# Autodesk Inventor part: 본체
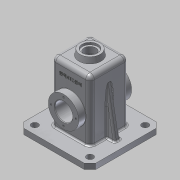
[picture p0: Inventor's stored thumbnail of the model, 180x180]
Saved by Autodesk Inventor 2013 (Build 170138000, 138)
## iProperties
Created: 2016-02
Part Number: 본체
Material: 알루미늄 6061
Document SubType Name: Modeling
Designer: dgall
Density: 2.71 g/cm^3
Mass: 931.159 g
Surface Area: 1047.57 cm^2
Volume: 343.601 cm^3
Author: dgall
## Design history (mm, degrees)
sketch "스케치1"
  geometry: L1 (-35, 65)-(35, 65); L2 (35, 65)-(35, -55); L3 (35, -55)-(-35, -55); L4 (-35, -55)-(-35, 65); 1 further point
  constraints: 8 end point, 2 parallel, 1 horizontal, 1 perpendicular
  dimensions: "d0" = 70 distance of L1.start L1.end; "d3" = 35 distance from line of point (0, 0) L4 (= 0.5 x d0); "d5" = 120 distance of L1.end L2.end; "d6" = 55 distance from line of L3 point (0, 0)
extrude "돌출1" new body sketch "스케치1" stored distance "d7" = 70; taper "d8" = 0 deg
feature "쉘1" dims "d9" = 5
sketch "스케치2"
  geometry: L1 (0, 68.106)-(0, 38.78); L2 (0, 75)-(18.237, 75); L3 (18.237, 75)-(20, 65); L4 (35, 65)-(-35, 65) reference; L5 (35, -55)-(35, 65) reference; L6 (0, 75)-(0, 65); L7 (20, 65)-(0, 65); 1 further point
  constraints: 10 end point, 2 point on line, 1 collinear, 1 midpoint, 1 perpendicular, 1 vertical, 1 vertical alignment
  dimensions: "d10" = 40 diameter of L3.end L1; "d12" = 10 distance between parallel lines of L4 L2; "d13" = 10 deg angle of L5 L3
revolve "회전1" sketch "스케치2" stored, may be unused: angle "d14" = 90 deg
sketch "스케치3"
  geometry: C1 r 18.237 at (0, 0) reference; C2 r 10.5 at (0, 0)
  constraints: 1 centre point, 1 coincident
  dimensions: "d15" = 21 diameter of C2
extrude "돌출2" cut sketch "스케치3" distance "d18" = 70; taper "d19" = 0 deg
sketch "스케치4"
  geometry: C1 r 10.5 at (0, 0) reference; C2 r 18.237 at (0, 0) reference; C3 r 14 at (0, 0)
  constraints: 1 centre point, 1 coincident
  dimensions: "d20" = 28 diameter of C3
extrude "돌출3" cut sketch "스케치4" distance "d22" = 4; taper "d23" = 0 deg
sketch "스케치5"
  geometry: L1 (70, 0)-(0, 0) reference; C1 r 16 at (35, 55); 1 further point
  constraints: 1 centre point, 1 coincident
  dimensions: "d24" = 32 diameter of C1; "d26" = 55 distance from line of L1 C1.centre (derived)
extrude "돌출4" cut sketch "스케치5" stored distance "d27" = 4; taper "d28" = 0 deg
sketch "스케치6"
  geometry: L1 (-35, 16)-(-30, 16) reference; L2 (-35, -55)-(-35, 65) reference; L3 (-30, -55)-(-30, 60) reference; L4 (-35, 27.5)-(-48, 27.5); L5 (-48, 27.5)-(-48, 16); L6 (-48, 16)-(-23, 16); L7 (-23, 16)-(-23, 20.5); L8 (-23, 20.5)-(-30, 27.5); L9 (-30, 27.5)-(-30, 16); L10 (-35, 27.5)-(-35, 16); L11 (0, 0)-(-45.049, 0); L12 (-35, 27.5)-(-30, 27.5); L13 (-35, 27.5)-(-30, 27.5)
  constraints: 20 end point, 5 perpendicular, 3 collinear, 3 point on line, 1 parallel
  dimensions: "d29" = 55 diameter of L4 L11; "d31" = 7 distance between parallel lines of L7 L3; "d32" = 13 distance between parallel lines of L2 L5; "d33" = 135 deg angle of L8 L3
revolve "회전2" sketch "스케치6" stored, may be unused: angle "d34" = 90 deg
sketch "스케치7" dims "d35" = 45
  geometry: C1 r 27.5 at (0, 0) reference; C2 r 16 at (0, 0) reference; C3 r 2 at (0, 22.5); 1 further point
  constraints: 2 vertical alignment, 1 centre point, 1 coincident, 2 other
  dimensions: "d37" = 4 diameter of C3
hole "구멍1" sketch "스케치7" at (0, 22.5) diameter "d38" = 3.242; stored, may be unused: countersink angle "d42" = 90 deg, drill point angle "d44" = 118 deg; dims "d39" = 8, "d40" = 4, "d41" = 2, "d43" = 10
sketch "스케치8"
  geometry: L1 (0, 0)-(70, 0) reference; L2 (0, -70)-(0, 0) reference; L3 (0, -70)-(70, -70) reference; L4 (70, 0)-(70, -70) reference; L5 (-30, 30)-(100, 30); L6 (100, 30)-(100, -100); L7 (100, -100)-(-30, -100); L8 (-30, -100)-(-30, 30); 1 further point
  constraints: 8 end point, 2 parallel, 1 horizontal, 1 perpendicular
  dimensions: "d48" = 130 distance of L5.start L5.end; "d50" = 130 distance between parallel lines of L7 L5; "d51" = 65 distance from line of point (35, -35) L5 (= 0.5 x d50); "d52" = 65 distance from line of point (35, -35) L8 (= 0.5 x d48)
extrude "돌출5" join sketch "스케치8" distance "d53" = 10; taper "d54" = 0 deg
chamfer "모따기1" distance "d55" = 10; stored, may be unused: second distance "d56" = 2, angle "d57" = 45 deg
sketch "스케치9"
  geometry: L1 (0, 0)-(110, 0) reference; L2 (-10, -120)-(-10, -10) reference; C1 r 6 at (5, -15); 1 further point
  constraints: 1 centre point
  dimensions: "d58" = 15 distance from line of C1.centre L1; "d59" = 15 distance from line of C1.centre L2; "d60" = 12 diameter of C1
extrude "돌출6" cut sketch "스케치9" distance "d61" = 10; taper "d62" = 0 deg
fillet "모깎기1" dims "d63" = 8
fillet "모깎기2" dims "d64" = 8
fillet "모깎기4" dims "d66" = 3
chamfer "모따기2" distance "d67" = 1; stored, may be unused: second distance "d68" = 2, angle "d69" = 45 deg
fillet "모깎기5" dims "d70" = 0.5
fillet "모깎기6" dims "d71" = 0.5
sketch "스케치10"
  geometry: L1 (7.59, -4.264)-(46.41, -4.264); L2 (46.41, -4.264)-(46.41, -19.736); L3 (46.41, -19.736)-(7.59, -19.736); L4 (7.59, -19.736)-(7.59, -4.264); L5 (7.59, -12)-(46.41, -12); L6 (27, -4.264)-(27, -19.736); L7 (8.763, 18)-(45.237, 18) reference; L8 (62, -102)-(62, 0) reference; 1 further point
  constraints: 4 end point, 4 midpoint, 2 other
  dimensions: "d72" = 30 distance between parallel lines of L5 L7; "d73" = 35 distance between parallel lines of L6 L8
extrude "돌출7" join sketch "스케치10" distance "d74" = 0.5; taper "d75" = 0 deg
sketch "스케치11"
  geometry: L1 (-35, 40.069)-(-50, -45); L2 (55, -45)-(-55, -45) reference; L3 (-35, -45)-(-35, 57) reference; L4 (-65, -45)-(-55, -45) reference; L5 (-55, -45)-(-55, -55) reference; L6 (-55, -55)-(-65, -55) reference; L7 (-65, -55)-(-65, -45) reference; L8 (44, -45)-(56, -45) reference; L9 (56, -55)-(44, -55) reference; L10 (55, -45)-(65, -45) reference; L11 (65, -45)-(65, -55) reference; L12 (65, -55)-(55, -55) reference; L13 (55, -55)-(55, -45) reference; L14 (35, 57)-(35, -45) reference; L15 (50, -45)-(35, 40.069); 3 further points
  constraints: 4 end point, 3 point on line, 1 midpoint
  dimensions: "d76" = 15 distance from line of L1.end L7; "d77" = 10 deg angle of L1 L7; "d78" = 15 distance from line of L15.start L11; "d79" = 10 deg angle of L15 L11
  node "투영된 루프1"
  node "투영된 루프2"
  node "투영된 루프3"
feature "리브1" dims "d80" = 1, "d81" = 10, "d82" = 0, "d83" = 0, "d84" = 1, "d85" = 1
feature "리브2" dims "d86" = 1, "d87" = 10, "d88" = 0, "d89" = 0, "d90" = 1, "d91" = 1
fillet "모깎기7" dims "d92" = 3
fillet "모깎기8" dims "d93" = 3
fillet "모깎기9" dims "d94" = 3
fillet "모깎기10" dims "d95" = 3
node "솔리드1"
pattern_circular "원형 패턴1" dims angle "d46" = 360 deg
mirror "대칭1"
mirror "대칭2"
mirror "대칭3"
